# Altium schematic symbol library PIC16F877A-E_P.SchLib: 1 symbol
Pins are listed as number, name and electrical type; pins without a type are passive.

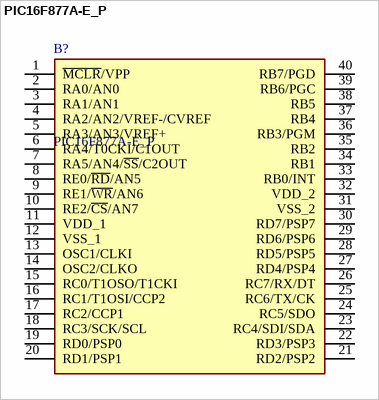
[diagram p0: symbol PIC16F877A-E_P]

## PIC16F877A-E_P
designator B?
8-bit Microcontrollers - MCU 14KB 368 RAM 33 I/O; Manufacturer_Name: Microchip; Manufacturer_Part_Number: PIC16F877A-E/P; Geometry.Height: 4.83mm
footprint DIP1550W56P254L5219H483Q40N
pins: 1 ~{MCLR}/VPP, 2 RA0/AN0, 3 RA1/AN1, 4 RA2/AN2/VREF-/CVREF, 5 RA3/AN3/VREF+, 6 RA4/T0CKI/C1OUT, 7 RA5/AN4/~{SS}/C2OUT, 8 RE0/~{RD}/AN5, 9 RE1/~{WR}/AN6, 10 RE2/~{CS}/AN7, 11 VDD_1, 12 VSS_1, 13 OSC1/CLKI, 14 OSC2/CLKO, 15 RC0/T1OSO/T1CKI, 16 RC1/T1OSI/CCP2, 17 RC2/CCP1, 18 RC3/SCK/SCL, 19 RD0/PSP0, 20 RD1/PSP1, 21 RD2/PSP2, 22 RD3/PSP3, 23 RC4/SDI/SDA, 24 RC5/SDO, 25 RC6/TX/CK, 26 RC7/RX/DT, 27 RD4/PSP4, 28 RD5/PSP5, 29 RD6/PSP6, 30 RD7/PSP7, 31 VSS_2, 32 VDD_2, 33 RB0/INT, 34 RB1, 35 RB2, 36 RB3/PGM, 37 RB4, 38 RB5, 39 RB6/PGC, 40 RB7/PGD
